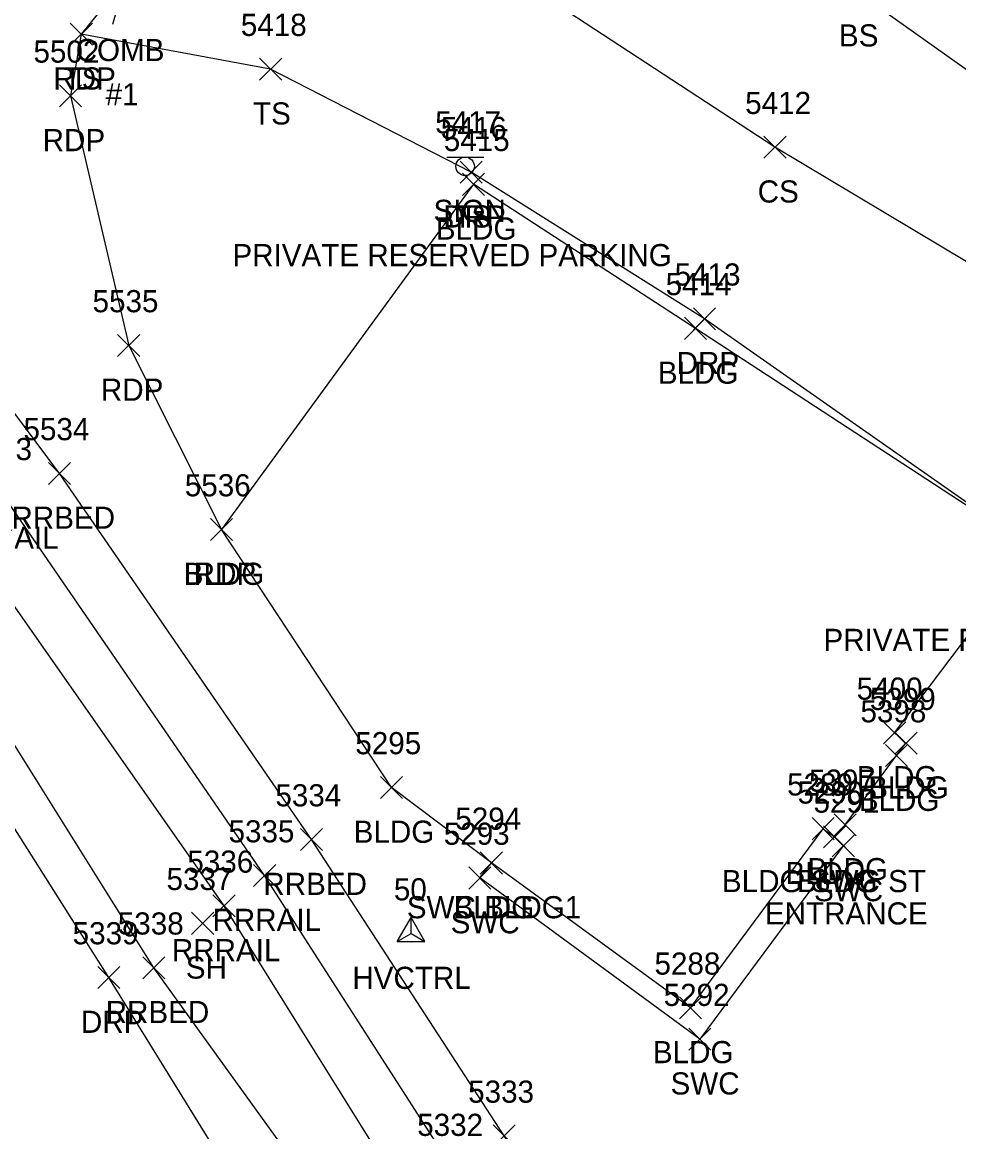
# Model space of a CAD drawing. Extents: x 1618146 to 1620418, y 640749 to 641927.
# Drawn here: x 1620219.4 to 1620304, y 641036.5 to 641136.7 of the extents above; entities that cross this region are included whole.
import ezdxf

# ---------------------------------------------------------------- set-up
doc = ezdxf.new("R2010")
doc.units = 0
for name, color, linetype in [('C_A', 7, 'Continuous'), ('C_I', 7, 'Continuous'), ('CPSM', 7, 'Continuous'), ('L_A', 7, 'Continuous'), ('L_C', 7, 'Continuous'), ('L_I', 7, 'Continuous'), ('L_TIC', 7, 'Continuous'), ('LBC', 7, 'Continuous'), ('LELB', 7, 'Continuous'), ('P_A', 7, 'Continuous'), ('P_I', 7, 'Continuous'), ('P_TIC', 7, 'Continuous'), ('PET', 7, 'Continuous'), ('R_A', 7, 'Continuous'), ('R_I', 7, 'Continuous'), ('R_TIC', 7, 'Continuous'), ('RDP', 7, 'Continuous'), ('RR', 7, 'Continuous'), ('RRB', 7, 'Continuous'), ('RSW', 7, 'Continuous'), ('S_A', 7, 'Continuous'), ('S_C', 7, 'Continuous'), ('S_I', 7, 'Continuous'), ('SSGN', 7, 'Continuous'), ('U_A', 7, 'Continuous'), ('U_C', 7, 'Continuous'), ('UP', 7, 'Continuous')]:
    doc.layers.add(name, color=color, linetype=linetype)

msp = doc.modelspace()

# ---------------------------------------------------------------- linework, layer by layer
at = {"layer": 'CPSM'}
for p, q in [((1620253.29, 641053.66), (1620254.54, 641055.83)), ((1620255.79, 641053.66), (1620254.54, 641055.83)), ((1620254.54, 641054.39), (1620254.54, 641055.83)), ((1620253.29, 641053.66), (1620254.54, 641054.39)), ((1620254.54, 641054.39), (1620254.54, 641054.39)), ((1620254.54, 641054.39), (1620255.79, 641053.66)), ((1620253.29, 641053.66), (1620255.79, 641053.66))]:
    msp.add_line(p, q, dxfattribs=at)
at = {"layer": 'L_TIC'}
for points in [[(1620223.76, 641134.64), (1620225.76, 641136.64)], [(1620225.76, 641134.64), (1620223.76, 641136.64)], [(1620240.86, 641131.48), (1620242.86, 641133.48)], [(1620242.86, 641131.48), (1620240.86, 641133.48)], [(1620286.41, 641124.43), (1620288.41, 641126.43)], [(1620288.41, 641124.43), (1620286.41, 641126.43)], [(1620258.98, 641122.17), (1620260.98, 641124.17)], [(1620260.98, 641122.17), (1620258.98, 641124.17)], [(1620259.19, 641121.08), (1620261.19, 641123.08)], [(1620261.19, 641121.08), (1620259.19, 641123.08)], [(1620279.23, 641108.06), (1620281.23, 641110.06)], [(1620281.23, 641108.06), (1620279.23, 641110.06)], [(1620236.42, 641089.89), (1620238.42, 641091.89)], [(1620238.42, 641089.89), (1620236.42, 641091.89)], [(1620236.42, 641089.89), (1620238.42, 641091.89)], [(1620238.42, 641089.89), (1620236.42, 641091.89)], [(1620297.22, 641071.52), (1620299.22, 641073.52)], [(1620299.22, 641071.52), (1620297.22, 641073.52)], [(1620298.24, 641070.59), (1620300.24, 641072.59)], [(1620300.24, 641070.59), (1620298.24, 641072.59)], [(1620297.39, 641069.47), (1620299.39, 641071.47)], [(1620299.39, 641069.47), (1620297.39, 641071.47)], [(1620251.77, 641066.59), (1620253.77, 641068.59)], [(1620253.77, 641066.59), (1620251.77, 641068.59)], [(1620290.77, 641062.86), (1620292.77, 641064.86)], [(1620292.77, 641062.86), (1620290.77, 641064.86)], [(1620292.75, 641063.21), (1620294.75, 641065.21)], [(1620294.75, 641063.21), (1620292.75, 641065.21)], [(1620291.8, 641062.13), (1620293.8, 641064.13)], [(1620293.8, 641062.13), (1620291.8, 641064.13)], [(1620260.8, 641059.77), (1620262.8, 641061.77)], [(1620262.8, 641059.77), (1620260.8, 641061.77)], [(1620234.72, 641054.32), (1620236.72, 641056.32)], [(1620236.72, 641054.32), (1620234.72, 641056.32)], [(1620278.79, 641046.68), (1620280.79, 641048.68)], [(1620280.79, 641046.68), (1620278.79, 641048.68)], [(1620278.79, 641046.68), (1620280.79, 641048.68)], [(1620280.79, 641046.68), (1620278.79, 641048.68)]]:
    msp.add_lwpolyline(points, dxfattribs=at)
at = {"layer": 'LBC'}
for points in [[(1620279.79, 641047.68), (1620291.77, 641063.86), (1620292.8, 641063.13), (1620293.75, 641064.21), (1620298.39, 641070.47), (1620299.24, 641071.59), (1620298.22, 641072.52), (1620309.74, 641087.78), (1620310.49, 641089.31), (1620280.23, 641109.06), (1620260.19, 641122.08), (1620237.42, 641090.89)], [(1620279.79, 641047.68), (1620261.8, 641060.77), (1620252.77, 641067.59), (1620237.42, 641090.89)]]:
    msp.add_lwpolyline(points, dxfattribs=at)
at = {"layer": 'LELB'}
for points in [[(1620328.73, 641115.39), (1620294.75, 641139.53), (1620257.99, 641160.06), (1620251.38, 641166.83)], [(1620310.49, 641089.31), (1620322.25, 641104.58), (1620287.41, 641125.43), (1620251.67, 641148.83), (1620241.33, 641155.99)], [(1620259.98, 641123.17), (1620241.86, 641132.48), (1620224.76, 641135.64)]]:
    msp.add_lwpolyline(points, dxfattribs=at)
at = {"layer": 'P_TIC'}
for points in [[(1620223.76, 641134.64), (1620225.76, 641136.64)], [(1620225.76, 641134.64), (1620223.76, 641136.64)], [(1620222.78, 641129.07), (1620224.78, 641131.07)], [(1620224.78, 641129.07), (1620222.78, 641131.07)], [(1620228.04, 641106.52), (1620230.04, 641108.52)], [(1620230.04, 641106.52), (1620228.04, 641108.52)], [(1620236.42, 641089.89), (1620238.42, 641091.89)], [(1620238.42, 641089.89), (1620236.42, 641091.89)]]:
    msp.add_lwpolyline(points, dxfattribs=at)
at = {"layer": 'PET'}
msp.add_lwpolyline([(1620264.26, 641193.84), (1620257.52, 641181.67), (1620253.5, 641174.42), (1620241.33, 641155.99), (1620224.76, 641135.64), (1620223.78, 641130.07), (1620229.04, 641107.52), (1620237.42, 641090.89)], dxfattribs=at)
at = {"layer": 'R_TIC'}
for points in [[(1620258.98, 641122.17), (1620260.98, 641124.17)], [(1620260.98, 641122.17), (1620258.98, 641124.17)], [(1620280.04, 641108.93), (1620282.04, 641110.93)], [(1620282.04, 641108.93), (1620280.04, 641110.93)], [(1620221.8, 641094.96), (1620223.8, 641096.96)], [(1620223.8, 641094.96), (1620221.8, 641096.96)], [(1620244.55, 641061.88), (1620246.55, 641063.88)], [(1620246.55, 641061.88), (1620244.55, 641063.88)], [(1620291.8, 641062.13), (1620293.8, 641064.13)], [(1620293.8, 641062.13), (1620291.8, 641064.13)], [(1620292.58, 641061.31), (1620294.58, 641063.31)], [(1620294.58, 641061.31), (1620292.58, 641063.31)], [(1620260.8, 641059.77), (1620262.8, 641061.77)], [(1620262.8, 641059.77), (1620260.8, 641061.77)], [(1620240.32, 641058.63), (1620242.32, 641060.63)], [(1620242.32, 641058.63), (1620240.32, 641060.63)], [(1620259.76, 641058.41), (1620261.76, 641060.41)], [(1620261.76, 641058.41), (1620259.76, 641060.41)], [(1620236.65, 641055.89), (1620238.65, 641057.89)], [(1620238.65, 641055.89), (1620236.65, 641057.89)], [(1620230.32, 641050.3), (1620232.32, 641052.3)], [(1620232.32, 641050.3), (1620230.32, 641052.3)], [(1620226.25, 641049.42), (1620228.25, 641051.42)], [(1620228.25, 641049.42), (1620226.25, 641051.42)], [(1620279.62, 641043.85), (1620281.62, 641045.85)], [(1620281.62, 641043.85), (1620279.62, 641045.85)], [(1620261.96, 641035.11), (1620263.96, 641037.11)], [(1620263.96, 641035.11), (1620261.96, 641037.11)]]:
    msp.add_lwpolyline(points, dxfattribs=at)
at = {"layer": 'RDP'}
for points in [[(1620310.49, 641089.31), (1620281.04, 641109.93), (1620259.98, 641123.17)], [(1620260.97, 640976.58), (1620260.23, 640976.78), (1620258.64, 640977.67), (1620254.7, 640981.22), (1620253.56, 640984.4), (1620254.45, 640989.13), (1620259.89, 640996.41), (1620260.58, 640997.17), (1620250.83, 641012.27), (1620227.25, 641050.42), (1620212.33, 641073.99), (1620204.63, 641086.97)]]:
    msp.add_lwpolyline(points, dxfattribs=at)
at = {"layer": 'RR'}
for points in [[(1620346.47, 640860.45), (1620330.76, 640897.47), (1620318, 640923.55), (1620306.67, 640947.65), (1620300.32, 640960.31), (1620293.94, 640972.26), (1620285.98, 640987.1), (1620281.46, 640995.25), (1620258.36, 641033.11), (1620241.32, 641059.63), (1620217.62, 641094.16), (1620201.56, 641115.97), (1620192.15, 641127.79), (1620168.31, 641155.99)], [(1620341.49, 640859.44), (1620326.2, 640895.4), (1620313.96, 640922.1), (1620303.21, 640943.7), (1620296.61, 640956.78), (1620290.44, 640967.96), (1620282.92, 640982.14), (1620278.2, 640990.78), (1620254.11, 641030.53), (1620237.65, 641056.89), (1620213.71, 641091.11), (1620198.15, 641113.29), (1620190.75, 641121.59), (1620164.76, 641152.66)]]:
    msp.add_lwpolyline(points, dxfattribs=at)
at = {"layer": 'RRB'}
for points in [[(1620282.83, 641005.9), (1620262.96, 641036.11), (1620245.55, 641062.88), (1620222.8, 641095.96), (1620205.8, 641118.71), (1620193.46, 641134.42), (1620171.4, 641158.88), (1620156.47, 641175.88), (1620136.03, 641194.9), (1620112.95, 641215.97), (1620104.58, 641223.13), (1620095.97, 641212.17)], [(1620271.86, 640991.56), (1620248.91, 641026.87), (1620231.32, 641051.3), (1620208.55, 641087.68), (1620199.84, 641100.89), (1620189.04, 641115.52), (1620174.38, 641133.16), (1620146.78, 641165.45), (1620126.45, 641185.25), (1620103.32, 641205.3), (1620095.97, 641212.17)]]:
    msp.add_lwpolyline(points, dxfattribs=at)
at = {"layer": 'RSW'}
msp.add_lwpolyline([(1620292.8, 641063.13), (1620293.58, 641062.31), (1620280.62, 641044.85), (1620260.76, 641059.41), (1620261.8, 641060.77)], dxfattribs=at)
at = {"layer": 'SSGN'}
for p, q in [((1620257.79, 641124.53), (1620261.12, 641124.53)), ((1620259.43, 641123.7), (1620259.43, 641123.7))]:
    msp.add_line(p, q, dxfattribs=at)
msp.add_circle((1620259.43, 641123.7), 0.833, dxfattribs=at)
at = {"layer": 'UP'}
msp.add_line((1620227.61, 641136.54), (1620227.86, 641137.38), dxfattribs=at)

# ---------------------------------------------------------------- texts
at = {"layer": 'C_A'}
msp.add_text('HVCTRL', height=2, dxfattribs=at).set_placement((1620249.24, 641049.39))
at = {"layer": 'C_I'}
msp.add_text('50', height=2, dxfattribs=at).set_placement((1620252.99, 641057.39))
at = {"layer": 'L_A'}
for s, p in [('BS', (1620293.19, 641134.53)), ('TS', (1620223.17, 641130.64)), ('TS', (1620240.27, 641127.48)), ('CS', (1620285.85, 641120.43)), ('TS', (1620258.38, 641118.17)), ('BLDG', (1620256.78, 641117.08)), ('BLDG', (1620276.83, 641104.06)), ('BLDG', (1620234.01, 641085.89)), ('BLDG', (1620234.01, 641085.89)), ('BLDG', (1620294.81, 641067.52)), ('BLDG', (1620295.83, 641066.59)), ('BLDG', (1620294.98, 641065.47)), ('BLDG', (1620249.36, 641062.59)), ('BLDG', (1620288.36, 641058.86)), ('BLDG', (1620290.34, 641059.21)), ('BLDG', (1620289.39, 641058.13)), ('BLDG', (1620258.39, 641055.77)), ('SH', (1620234.2, 641050.32)), ('BLDG', (1620276.38, 641042.68)), ('BLDG', (1620276.38, 641042.68))]:
    msp.add_text(s, height=2, dxfattribs=at).set_placement(p)
at = {"layer": 'L_C'}
msp.add_text('ENTRANCE', height=2, dxfattribs=at).set_placement((1620286.5, 641055.21))
at = {"layer": 'L_I'}
for s, p in [('5418', (1620239.17, 641135.48)), ('5412', (1620284.72, 641128.43)), ('5416', (1620257.23, 641126.17)), ('5415', (1620257.5, 641125.08)), ('5414', (1620277.54, 641112.06)), ('5536', (1620234.11, 641093.89)), ('5536', (1620234.11, 641093.89)), ('5400', (1620294.79, 641075.52)), ('5399', (1620295.98, 641074.59)), ('5398', (1620295.13, 641073.47)), ('5295', (1620249.51, 641070.59)), ('5289', (1620288.51, 641066.86)), ('5397', (1620290.49, 641067.21)), ('5290', (1620289.45, 641066.13)), ('5294', (1620258.54, 641063.77)), ('5337', (1620232.46, 641058.32)), ('5288', (1620276.53, 641050.68)), ('5288', (1620276.53, 641050.68))]:
    msp.add_text(s, height=2, dxfattribs=at).set_placement(p)
at = {"layer": 'P_A'}
for p in [(1620222.24, 641130.64), (1620221.27, 641125.07), (1620226.53, 641102.52), (1620234.91, 641085.89)]:
    msp.add_text('RDP', height=2, dxfattribs=at).set_placement(p)
at = {"layer": 'P_I'}
for s, p in [('5502', (1620220.44, 641133.07)), ('5535', (1620225.78, 641110.52)), ('5536', (1620234.11, 641093.89))]:
    msp.add_text(s, height=2, dxfattribs=at).set_placement(p)
at = {"layer": 'R_A'}
for s, p in [('DRP', (1620257.46, 641118.17)), ('DRP', (1620278.53, 641104.93)), ('RRBED', (1620218.45, 641090.96)), ('RRRAIL', (1620212.91, 641089.16)), ('RRBED', (1620241.2, 641057.88)), ('BLDG SWC ST', (1620282.62, 641058.13)), ('SWC', (1620290.94, 641057.31)), ('SWC BLDG1', (1620254.16, 641055.77)), ('RRRAIL', (1620236.61, 641054.63)), ('SWC', (1620258.12, 641054.41)), ('RRRAIL', (1620232.94, 641051.89)), ('RRBED', (1620226.96, 641046.3)), ('DRP', (1620224.73, 641045.42)), ('SWC', (1620277.98, 641039.85))]:
    msp.add_text(s, height=2, dxfattribs=at).set_placement(p)
at = {"layer": 'R_I'}
for s, p in [('5416', (1620257.23, 641126.17)), ('5413', (1620278.35, 641112.93)), ('5534', (1620219.54, 641098.96)), ('5533', (1620214.36, 641097.16)), ('5334', (1620242.29, 641065.88)), ('5290', (1620289.45, 641066.13)), ('5291', (1620290.89, 641065.31)), ('5294', (1620258.54, 641063.77)), ('5335', (1620238.06, 641062.63)), ('5293', (1620257.5, 641062.41)), ('5336', (1620234.34, 641059.89)), ('5338', (1620228.06, 641054.3)), ('5339', (1620223.98, 641053.42)), ('5292', (1620277.36, 641047.85)), ('5333', (1620259.7, 641039.11)), ('5332', (1620255.1, 641036.11))]:
    msp.add_text(s, height=2, dxfattribs=at).set_placement(p)
at = {"layer": 'S_A'}
msp.add_text('SIGN', height=2, dxfattribs=at).set_placement((1620256.57, 641118.68))
at = {"layer": 'S_C'}
for p in [(1620238.41, 641114.68), (1620291.79, 641079.92)]:
    msp.add_text('PRIVATE RESERVED PARKING', height=2, dxfattribs=at).set_placement(p)
at = {"layer": 'S_I'}
msp.add_text('5417', height=2, dxfattribs=at).set_placement((1620256.72, 641126.68))
at = {"layer": 'U_A'}
msp.add_text('COMB', height=2, dxfattribs=at).set_placement((1620224.25, 641133.21))
at = {"layer": 'U_C'}
msp.add_text('#1', height=2, dxfattribs=at).set_placement((1620226.96, 641129.21))

doc.saveas('drawing.dxf')
